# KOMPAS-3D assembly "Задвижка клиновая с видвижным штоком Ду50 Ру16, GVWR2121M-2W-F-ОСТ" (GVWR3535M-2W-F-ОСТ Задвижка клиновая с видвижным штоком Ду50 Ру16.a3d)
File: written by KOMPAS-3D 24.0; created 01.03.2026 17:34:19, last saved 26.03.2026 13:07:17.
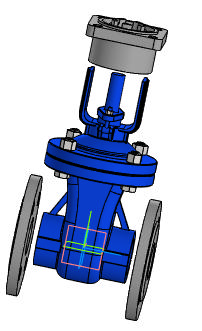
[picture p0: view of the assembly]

Document properties: Автор: R2D2; Полное имя файла: E:\Работа\Зайцев\GVWR2121M-2W-F-ОСТ Задвижка клиновая с видвижным штоком Ду50-300 Ру16\DN50\Исходные материалы\GVWR2121M-2W-F-ОСТ Задвижка клиновая с видвижным штоком Ду50 Ру16.a3d

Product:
- Component [detail]: AS 1110 - M12 x 45  | qty 4  | pos. 2  | Масса: 0.056439; Комментарий: Болты и винты   шестигранные точные   метрические ISO; Автор: R2D2; additional columns: Сталь, мягкая; source file: AS 1110 - M12 x 45 AS 1110 - M12 x 45.m3d
- Component [detail]: ANSI B18.2.4.2M - M12x1,75 - 18  | designation ANSI B18.2.4.2M - M12x1,75  | qty 4  | pos. 3  | Масса: 0.018772; Комментарий: Типы метрических   шестигранных гаек   2; Автор: R2D2; additional columns: Сталь, мягкая; source file: ANSI B18.2.4.2M - M12x1,75 ANSI B18.2.4.2M - M12x1,75 - 18.m3d
- Component [detail]: ANSI B18.2.4.2M - M5x0,8 - 8  | designation ANSI B18.2.4.2M - M5x0,8  | qty 1  | pos. 4  | Масса: 0.00167; Комментарий: Типы метрических   шестигранных гаек   2; Автор: R2D2; additional columns: Сталь, мягкая; source file: ANSI B18.2.4.2M - M5x0,8 ANSI B18.2.4.2M - M5x0,8 - 8.m3d
- Component [detail]: Деталь1  | qty 1  | pos. 5  | Масса: 12.23036; Автор: R2D2; additional columns: Типовые; source file: 2.m3d
- Component [detail]: Фланец  | qty 1  | pos. 5  | Масса: 2.041312; Автор: R2D2; additional columns: Типовые; source file: Фланец DN50 PN16 D160 b17.m3d
- Component [detail]: Фланец  | designation 01  | qty 1  | pos. 6  | Масса: 2.041312; additional columns: Типовые; source file: Фланец DN50 PN16 D160 b17.m3d
- Component [detail]: ANSI B18.2.4.2M - M5x0,8 - 8  | designation ANSI B18.2.4.2M - M5x0,8-01  | qty 1  | pos. 7  | Масса: 0.00167; Комментарий: Типы метрических   шестигранных гаек   2; Автор: R2D2; additional columns: Сталь, мягкая; source file: ANSI B18.2.4.2M - M5x0,8 ANSI B18.2.4.2M - M5x0,8 - 8.m3d
- Component [assembly]: DN50_3D_STEP  | designation Сборка  | qty 1  | Масса: 2.725126; Автор: R2D2; source file: Фланец А.a3d
- Part/product: Задвижка клиновая с видвижным штоком Ду50 Ру16  | designation GVWR2121M-2W-F-ОСТ
    Масса: 12
    Раздел спецификации: Прочие изделия
    Примечание: D040-08598

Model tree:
1. Массив по концентрической сетке:1  (with: Грань.Элемент вращения:1, Грань.Операция без истории:2)  (labels: Грань.Твердое тело1; Грань.Solid1)  (4 pattern instances)
     Шаг 2 = 360; Расстояние = -90; Ориентация = 2; Ориентация = 2; Расстояние = -305

Referenced files in E:\Работа\Зайцев\GVWR2121M-2W-F-ОСТ Задвижка клиновая с видвижным штоком Ду50-300 Ру16\DN50\Исходные материалы\: AS 1110 - M12 x 45 AS 1110 - M12 x 45.m3d, ANSI B18.2.4.2M - M12x1,75 ANSI B18.2.4.2M - M12x1,75 - 18.m3d, ANSI B18.2.4.2M - M5x0,8 ANSI B18.2.4.2M - M5x0,8 - 8.m3d, 2.m3d, Фланец DN50 PN16 D160 b17.m3d, Фланец А.a3d
Referenced files in E:\Работа\Зайцев\GVWR3131M-2W-F-S Задвижка клиновая с выдвижным штоком DN.ru Ду50-200 Ру63\DN50\исходные материалы\: ANSI B18.2.4.2M - M12x1,75 ANSI B18.2.4.2M - M12x1,75 - 18.m3d, AS 1110 - M12 x 45 AS 1110 - M12 x 45.m3d
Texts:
  Программные изделия  и базы данных
  ANSI B18.2.4.2M - M12x1,75
  ANSI B18.2.4.2M - M5x0,8
  ANSI B18.2.4.2M - M5x0,8 - 01
  ANSI B18.2.4.2M - M5x0,8-01
  GVWR2121M-2W-F-ОСТ
  AS 1110 - M12 x 45 AS 1110 - M12 x 45 (1)
  ANSI B18.2.4.2M - M12x1,75 ANSI B18.2.4.2M - M12x1,75 - 18 (1)
  ANSI B18.2.4.2M - M5x0,8 ANSI B18.2.4.2M - M5x0,8 - 8
  Деталь1 Деталь1
  ANSI B18.2.4.2M - M12x1,75 ANSI B18.2.4.2M - M12x1,75 - 18 (2)
  AS 1110 - M12 x 45 AS 1110 - M12 x 45 (2)
  ANSI B18.2.4.2M - M12x1,75 ANSI B18.2.4.2M - M12x1,75 - 18 (3)
  AS 1110 - M12 x 45 AS 1110 - M12 x 45 (3)
  ANSI B18.2.4.2M - M12x1,75 ANSI B18.2.4.2M - M12x1,75 - 18 (4)
  AS 1110 - M12 x 45 AS 1110 - M12 x 45 (4)
  ANSI B18.2.4.2M - M5x0,8-01 ANSI B18.2.4.2M - M5x0,8 - 8
  Сборка DN50_3D_STEP
  Ось Y.Начало координат
  Ось Z.Начало координат
  Плоскость ZX.Начало координат
  Плоскость XY.Начало координат
  Плоскость ZY.Начало координат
